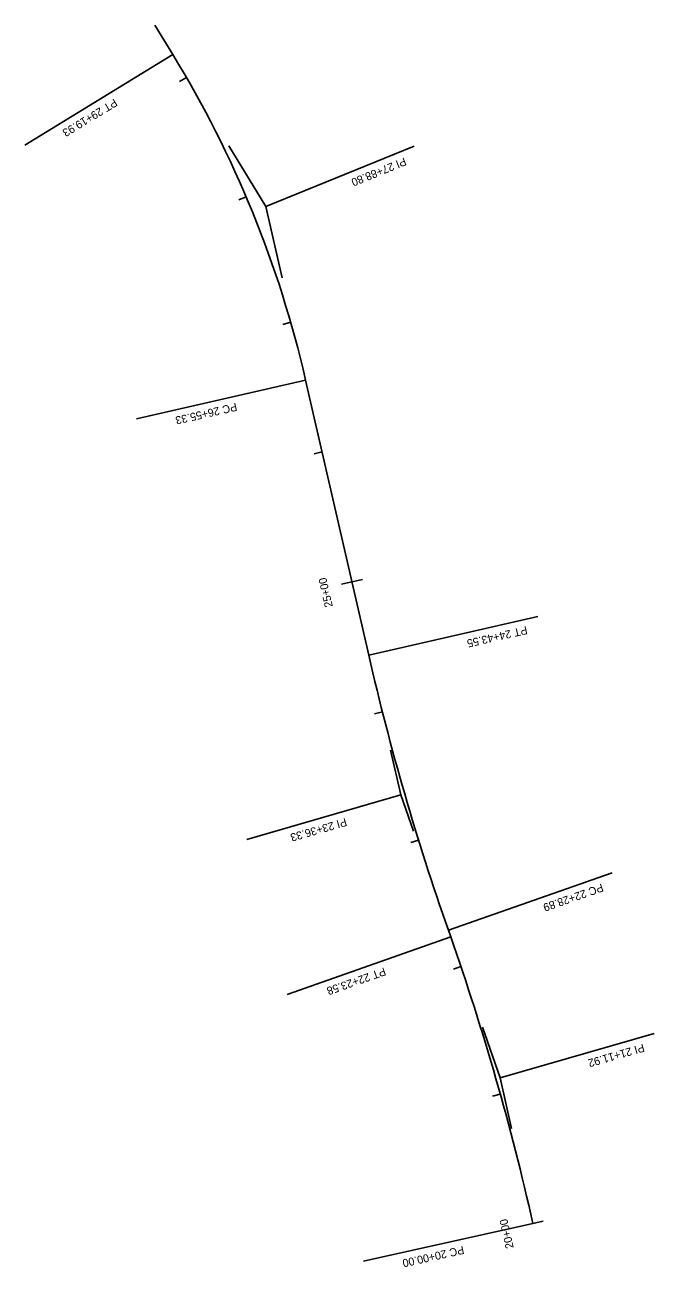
# Model space of a CAD drawing. Extents: x 955367 to 987800, y 1869413 to 1923417.
# Drawn here: x 957608 to 958080, y 1919040 to 1919971 of the extents above; entities that cross this region are included whole.
import ezdxf

# ---------------------------------------------------------------- set-up
doc = ezdxf.new("R2010")
doc.units = 0
doc.layers.add('R_Horz Alg', color=7, linetype='Continuous')
doc.layers.add('R_Horz Alg Annot', color=7, linetype='Continuous')

msp = doc.modelspace()

# ---------------------------------------------------------------- linework, layer by layer
at = {"layer": 'R_Horz Alg'}
for p, q in [((957719.29, 1919948.69), (957705.82, 1919970.74)), ((957866.07, 1919498.31), (957818.74, 1919704.73)), ((957927.46, 1919287.21), (957925.7, 1919292.21))]:
    msp.add_line(p, q, dxfattribs=at)
for centre, radius, start, end in [((957020.93, 1919521.78), 818.51, 12.91576, 31.43797), ((959727.61, 1919925.2), 1909.86, 192.91576, 199.35559), ((956125.54, 1918654.22), 1909.86, 12.64806, 19.35559)]:
    msp.add_arc(centre, radius, start, end, dxfattribs=at)
at = {"layer": 'R_Horz Alg Annot'}
for p, q in [((957788.9, 1919834.82), (957761.09, 1919880.32)), ((957801.19, 1919781.26), (957788.9, 1919834.82)), ((957882.37, 1919427.24), (957890.09, 1919393.58)), ((957899.62, 1919366.45), (957890.09, 1919393.58)), ((957964.55, 1919181.61), (957951.24, 1919219.5)), ((957973.12, 1919143.42), (957964.55, 1919181.61))]:
    msp.add_line(p, q, dxfattribs=at)
for points in [[(957719.29, 1919948.69), (957608.37, 1919880.89)], [(957724.29, 1919928.56), (957729.48, 1919931.56)], [(957788.9, 1919834.82), (957900.03, 1919880.11)], [(957768.62, 1919839.81), (957774.14, 1919842.15)], [(957801.8, 1919746.32), (957807.57, 1919747.97)], [(957818.74, 1919704.73), (957692.02, 1919675.67)], [(957825.25, 1919649.46), (957831.1, 1919650.8)], [(957845.66, 1919551.54), (957861.25, 1919555.12)], [(957866.07, 1919498.31), (957992.78, 1919527.36)], [(957870.47, 1919454.5), (957876.29, 1919455.97)], [(957890.09, 1919393.58), (957774.81, 1919360.23)], [(957897.65, 1919357.95), (957903.38, 1919359.73)], [(957925.7, 1919292.21), (958048.35, 1919335.3)], [(957927.46, 1919287.21), (957804.8, 1919244.12)], [(957929.45, 1919262.99), (957935.14, 1919264.91)], [(957964.55, 1919181.61), (958079.9, 1919214.69)], [(957958.84, 1919167.74), (957964.62, 1919169.36)], [(957989.06, 1919072.41), (957862.21, 1919043.94)], [(957981.25, 1919070.66), (957996.86, 1919074.16)]]:
    msp.add_lwpolyline(points, dxfattribs=at)

# ---------------------------------------------------------------- texts
at = {"layer": 'R_Horz Alg'}
for rotation, p in [(121.43797, (957706.47, 1919970.63)), (121.43797, (957719.94, 1919948.59)), (102.91576, (957819.32, 1919704.42)), (102.91576, (957866.66, 1919498)), (109.35559, (957926.31, 1919291.97)), (109.35559, (957928.07, 1919286.97)), (102.64806, (957989.64, 1919072.1))]:
    msp.add_text('+', height=1, rotation=rotation, dxfattribs=at).set_placement(p)
at = {"layer": 'R_Horz Alg Annot'}
for s, rotation, p in [('PT 29+19.93', 211.43797, (957675.29, 1919915.93)), ('PI 27+88.80', 202.17687, (957892.65, 1919871.71)), ('PC 26+55.33', 192.91576, (957766.61, 1919687.65)), ('25+00', 102.91576, (957839.18, 1919535.03)), ('PT 24+43.55', 192.91576, (957984.15, 1919520.26)), ('PI 23+36.33', 196.13568, (957848.61, 1919376.38)), ('PC 22+28.89', 199.35559, (958040.57, 1919327.27)), ('PT 22+23.58', 199.35559, (957877.55, 1919264.37)), ('PI 21+11.92', 196.00182, (958071.67, 1919207.13)), ('20+00', 102.64806, (957974.7, 1919054.18)), ('PC 20+00.00', 192.64806, (957936.77, 1919055.55))]:
    msp.add_text(s, height=6, rotation=rotation, dxfattribs=at).set_placement(p)

doc.saveas('drawing.dxf')
